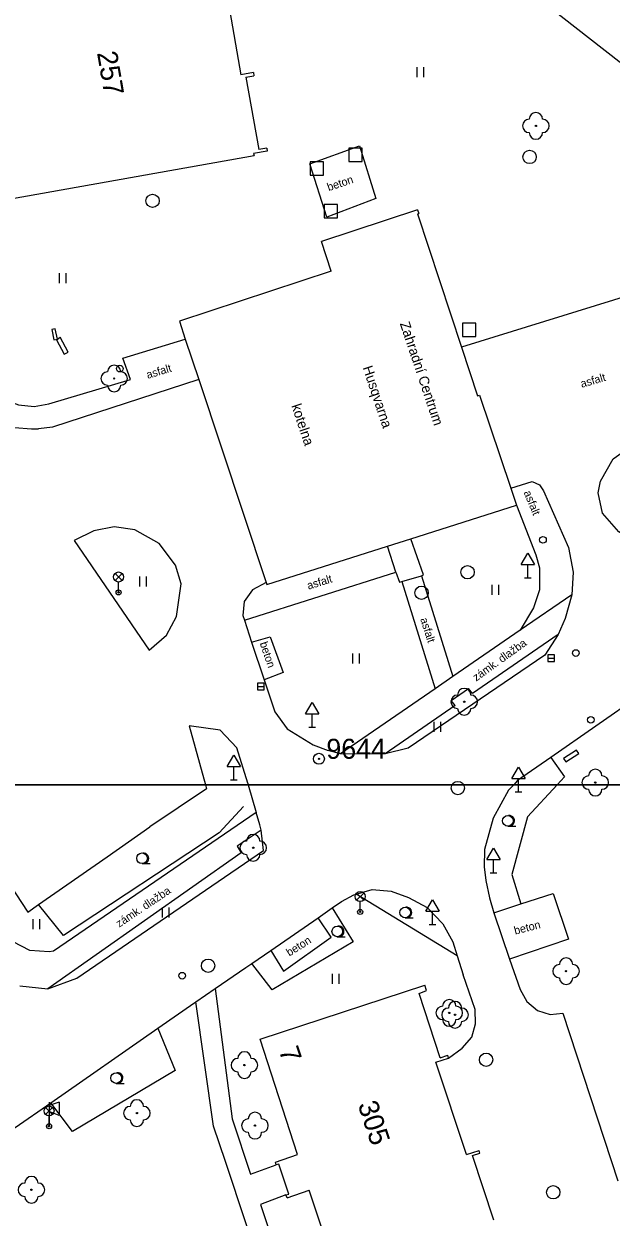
# Model space of a CAD drawing. Extents: x -492431 to -49218, y -1127123 to -112687.
# Drawn here: x -492287 to -492243, y -1127032.4 to -1126943 of the extents above; entities that cross this region are included whole.
import ezdxf

# ---------------------------------------------------------------- set-up
doc = ezdxf.new("R2010")
doc.units = 0
for name, color, linetype in [('Vrstva 10', 7, 'Continuous'), ('Vrstva 11', 7, 'Continuous'), ('Vrstva 21', 7, 'Continuous'), ('Vrstva 22', 7, 'Continuous'), ('Vrstva 24', 7, 'Continuous'), ('Vrstva 26', 7, 'Continuous'), ('Vrstva 27', 7, 'Continuous'), ('Vrstva 28', 7, 'Continuous'), ('Vrstva 31', 7, 'Continuous'), ('Vrstva 33', 7, 'Continuous'), ('Vrstva 34', 7, 'Continuous'), ('Vrstva 36', 7, 'Continuous'), ('Vrstva 40', 7, 'Continuous'), ('Vrstva 41', 7, 'Continuous'), ('Vrstva 43', 7, 'Continuous'), ('Vrstva 44', 7, 'Continuous'), ('Vrstva 5', 7, 'Continuous'), ('Vrstva 60', 7, 'Continuous'), ('Vrstva 63', 7, 'Continuous')]:
    doc.layers.add(name, color=color, linetype=linetype)

msp = doc.modelspace()

# ---------------------------------------------------------------- linework, layer by layer
at = {"layer": 'Vrstva 10'}
for p, q in [((-492265.6, -1126953.46), (-492261.86, -1126952.11)), ((-492261.86, -1126952.11), (-492260.64, -1126956.06)), ((-492264.31, -1126957.46), (-492265.6, -1126953.46)), ((-492260.64, -1126956.06), (-492264.31, -1126957.46)), ((-492279.61, -1126968.02), (-492274.92, -1126966.59)), ((-492279.03, -1126969.62), (-492279.61, -1126968.02)), ((-492285.15, -1126971.46), (-492279.03, -1126969.62)), ((-492287.72, -1126973.22), (-492286.45, -1126973.32)), ((-492286.45, -1126973.32), (-492285.91, -1126973.32)), ((-492281.77, -1126980.96), (-492283.25, -1126981.69)), ((-492280.25, -1126980.68), (-492281.77, -1126980.96)), ((-492278.7, -1126980.9), (-492280.25, -1126980.68)), ((-492276.87, -1126981.91), (-492278.7, -1126980.9)), ((-492283.25, -1126981.69), (-492277.62, -1126989.91)), ((-492275.66, -1126983.54), (-492276.87, -1126981.91)), ((-492275.23, -1126984.94), (-492275.66, -1126983.54)), ((-492275.57, -1126987.38), (-492275.23, -1126984.94)), ((-492245.95, -1126985.77), (-492246.47, -1126987.55)), ((-492276.32, -1126988.78), (-492275.57, -1126987.38)), ((-492246.47, -1126987.55), (-492246.98, -1126988.75)), ((-492277.62, -1126989.91), (-492276.32, -1126988.78)), ((-492246.98, -1126988.75), (-492253.39, -1126993.17)), ((-492246.98, -1126988.75), (-492247.98, -1126990.28)), ((-492247.98, -1126990.28), (-492258.22, -1126997.26)), ((-492255.01, -1126993.69), (-492253.69, -1126992.79)), ((-492253.39, -1126993.17), (-492253.69, -1126992.79)), ((-492254.71, -1126994.07), (-492259.95, -1126997.69)), ((-492254.71, -1126994.07), (-492255.01, -1126993.69)), ((-492261.1, -1126997.72), (-492263.3, -1126997.68)), ((-492259.95, -1126997.69), (-492261.1, -1126997.72)), ((-492258.22, -1126997.26), (-492259.95, -1126997.69)), ((-492270.23, -1126999.88), (-492270.2, -1127000)), ((-492270.2, -1127000), (-492269.62, -1127002.09)), ((-492269.62, -1127002.09), (-492284.8, -1127012.48)), ((-492269.34, -1127003.02), (-492269.62, -1127002.09)), ((-492280.77, -1127005.41), (-492277.57, -1127003.17)), ((-492269.24, -1127003.41), (-492269.34, -1127003.02)), ((-492269.24, -1127003.41), (-492271.04, -1127004.61)), ((-492269.06, -1127004.93), (-492269.24, -1127003.41)), ((-492270.73, -1127005.1), (-492285.22, -1127015.31)), ((-492283.04, -1127014.51), (-492269.06, -1127004.93)), ((-492271.04, -1127004.61), (-492270.73, -1127005.1)), ((-492286.57, -1127012.44), (-492287.83, -1127011.78)), ((-492285.11, -1127012.53), (-492286.57, -1127012.44)), ((-492284.8, -1127012.48), (-492285.11, -1127012.53)), ((-492285.22, -1127015.31), (-492283.04, -1127014.51)), ((-492287.32, -1127015.07), (-492285.22, -1127015.31))]:
    msp.add_line(p, q, dxfattribs=at)
for points in [[(-492272.49, -1126922.14), (-492263.24, -1126929.48), (-492236.88, -1126950.1), (-492234.89, -1126951.93), (-492232.6, -1126954.06), (-492229.07, -1126957.73), (-492220.98, -1126966.9), (-492221, -1126967.98), (-492221.64, -1126968.8), (-492231.06, -1126975.34), (-492237.59, -1126979.85), (-492240.73, -1126982.05)], [(-492291.44, -1126950.48), (-492294.66, -1126951.12), (-492295.46, -1126951.82), (-492295.99, -1126953.28), (-492294.2, -1126958.55), (-492290.72, -1126968.68), (-492290.05, -1126969.86), (-492288.83, -1126971), (-492287.42, -1126971.52), (-492286.24, -1126971.66), (-492285.15, -1126971.46)], [(-492240.73, -1126982.05), (-492242.43, -1126981.04), (-492243.65, -1126979.65), (-492243.98, -1126978.13), (-492243.82, -1126977.24), (-492242.86, -1126975.57), (-492242.18, -1126975.1), (-492234.4, -1126972.49), (-492237.99, -1126962.18), (-492254.22, -1126967.21)], [(-492273.91, -1126969.62), (-492284.88, -1126973.2), (-492285.91, -1126973.32)], [(-492250.54, -1126977.76), (-492248.94, -1126977.27), (-492248.39, -1126977.51), (-492248.07, -1126977.98), (-492246.22, -1126982.22), (-492245.86, -1126984.06), (-492245.95, -1126985.77)], [(-492250.11, -1126979.04), (-492248.65, -1126982.76), (-492248.39, -1126983.74), (-492248.37, -1126985.38), (-492248.82, -1126986.74), (-492249.82, -1126988.41), (-492254.88, -1126991.89)], [(-492257.22, -1126984.35), (-492257.08, -1126984.27), (-492258.02, -1126981.56)], [(-492270.49, -1126987.67), (-492259.15, -1126984.07)], [(-492259.15, -1126984.07), (-492258.86, -1126984.82), (-492258.69, -1126984.76)], [(-492257.22, -1126984.35), (-492254.88, -1126991.89)], [(-492268.86, -1126984.83), (-492269.88, -1126985.38), (-492270.51, -1126986.26), (-492270.61, -1126987.31)], [(-492258.69, -1126984.76), (-492256.2, -1126992.81)], [(-492270.61, -1126987.31), (-492270.49, -1126987.67)], [(-492270.49, -1126987.67), (-492269.96, -1126989.31)], [(-492269.96, -1126989.31), (-492268.56, -1126988.92), (-492267.59, -1126991.6), (-492269, -1126992.13)], [(-492269.96, -1126989.31), (-492269, -1126992.13), (-492268.21, -1126994.53), (-492267.29, -1126995.81), (-492265.34, -1126997.02), (-492264.22, -1126997.44)], [(-492237.41, -1126990.92), (-492247.53, -1126997.96), (-492250.02, -1126999.69)], [(-492256.2, -1126992.81), (-492263.3, -1126997.68)], [(-492270.23, -1126999.88), (-492271.07, -1126997.24), (-492272.31, -1126995.92), (-492274.63, -1126995.59), (-492273.41, -1127000)], [(-492263.3, -1126997.68), (-492264.22, -1126997.44)], [(-492250.02, -1126999.69), (-492250.31, -1127000)], [(-492273.41, -1127000), (-492273.32, -1127000.31), (-492277.57, -1127003.17)], [(-492250.31, -1127000), (-492250.71, -1127000.42), (-492251.85, -1127002.52), (-492252.49, -1127004.86), (-492252.53, -1127006.16), (-492252.4, -1127007.18), (-492252.12, -1127008.48), (-492251.8, -1127009.61)], [(-492289.34, -1127005.59), (-492286.73, -1127009.56), (-492285.91, -1127008.99), (-492280.77, -1127005.41)], [(-492264.97, -1127009.97), (-492263.91, -1127009.24), (-492263.22, -1127008.76), (-492262.3, -1127008.27), (-492262.13, -1127008.22), (-492260.93, -1127007.87), (-492259.5, -1127007.99), (-492258.19, -1127008.45), (-492256.79, -1127009.2), (-492255.63, -1127010.42), (-492254.87, -1127011.79), (-492254.54, -1127012.84), (-492254.09, -1127014.25)], [(-492251.8, -1127009.61), (-492249.77, -1127008.94), (-492247.36, -1127008.15), (-492246.22, -1127011.59), (-492250.62, -1127013.07)], [(-492251.8, -1127009.61), (-492250.62, -1127013.07), (-492249.84, -1127015.35), (-492249.33, -1127016.26), (-492248.54, -1127016.92), (-492247.57, -1127017.23), (-492246.64, -1127017.13), (-492242.51, -1127029.7)], [(-492268.5, -1127012.44), (-492267.56, -1127013.99), (-492263.99, -1127011.44), (-492264.97, -1127009.97)], [(-492268.5, -1127012.44), (-492264.97, -1127009.97)], [(-492288.26, -1127040.02), (-492289.42, -1127036.56), (-492289.89, -1127035.11), (-492290.26, -1127032.72), (-492290.1, -1127029.83), (-492289.45, -1127028.22), (-492288.65, -1127026.91), (-492287.66, -1127025.7), (-492284.99, -1127023.84), (-492276.97, -1127018.26), (-492274.21, -1127016.34), (-492274.13, -1127016.28), (-492272.68, -1127015.29), (-492270.39, -1127013.71), (-492269.93, -1127013.4), (-492268.5, -1127012.44)], [(-492255.2, -1127020.49), (-492254.18, -1127019.76), (-492253.46, -1127018.94), (-492253.17, -1127017.94), (-492253.21, -1127016.86), (-492254.09, -1127014.25)], [(-492272.68, -1127015.29), (-492271.4, -1127025.05), (-492270.03, -1127029.19), (-492268.1, -1127028.5)], [(-492271.91, -1127028.26), (-492272.82, -1127025.61), (-492274.13, -1127016.28)], [(-492259.59, -1127065.402), (-492271.91, -1127028.26)], [(-492267.38, -1127030.76), (-492269.28, -1127031.47), (-492265.13, -1127043.91), (-492264.31, -1127046.41), (-492262.43, -1127045.76)]]:
    msp.add_lwpolyline(points, dxfattribs=at)
at = {"layer": 'Vrstva 11'}
for points in [[(-492259.15, -1126984.07), (-492259.77, -1126982.12)], [(-492258.69, -1126984.76), (-492257.22, -1126984.35)], [(-492245.95, -1126985.77), (-492249.82, -1126988.41)], [(-492254.88, -1126991.89), (-492256.2, -1126992.81)]]:
    msp.add_lwpolyline(points, dxfattribs=at)
at = {"layer": 'Vrstva 21'}
for points in [[(-492247.53, -1126997.96), (-492246.5, -1126999.4), (-492247.05, -1127000)], [(-492247.05, -1127000), (-492249.28, -1127002.42), (-492250.45, -1127006.73), (-492249.77, -1127008.94)], [(-492270.55, -1127001.64), (-492272.38, -1127003.62), (-492284.04, -1127011.31), (-492285.91, -1127008.99)], [(-492254.54, -1127012.84), (-492262.13, -1127008.22)], [(-492263.91, -1127009.24), (-492262.34, -1127011.79), (-492268.42, -1127015.38), (-492269.93, -1127013.4)], [(-492276.97, -1127018.26), (-492275.68, -1127021.43), (-492283.38, -1127025.99), (-492284.99, -1127023.84)]]:
    msp.add_lwpolyline(points, dxfattribs=at)
at = {"layer": 'Vrstva 22'}
for centre in [(-492248.65, -1126950.61), (-492280.25, -1126969.55), (-492254.02, -1126993.78), (-492244.2, -1126999.84), (-492269.83, -1127004.73), (-492246.39, -1127013.98), (-492255.14, -1127017.11), (-492254.71, -1127017.25), (-492270.49, -1127021.02), (-492278.55, -1127024.62), (-492269.7, -1127025.56), (-492286.45, -1127030.37)]:
    msp.add_circle(centre, 0.05, dxfattribs=at)
for centre, start, end in [((-492248.65, -1126950.11), 360, 180), ((-492249.15, -1126950.61), 90, 270), ((-492248.15, -1126950.61), 270, 90), ((-492248.65, -1126951.11), 180, 0), ((-492280.75, -1126969.55), 90, 270), ((-492280.25, -1126969.05), 360, 180), ((-492279.75, -1126969.55), 270, 90), ((-492280.25, -1126970.05), 180, 0), ((-492254.52, -1126993.78), 90, 270), ((-492254.02, -1126993.28), 360, 180), ((-492253.52, -1126993.78), 270, 90), ((-492254.02, -1126994.28), 180, 0), ((-492244.2, -1126999.34), 360, 180), ((-492244.7, -1126999.84), 90, 270), ((-492243.7, -1126999.84), 270, 90), ((-492244.2, -1127000.34), 180, 0), ((-492270.33, -1127004.73), 90, 270), ((-492269.83, -1127004.23), 360, 180), ((-492269.33, -1127004.73), 270, 90), ((-492269.83, -1127005.23), 180, 0), ((-492246.39, -1127013.48), 360, 180), ((-492246.89, -1127013.98), 90, 270), ((-492245.89, -1127013.98), 270, 90), ((-492246.39, -1127014.48), 180, 0), ((-492255.64, -1127017.11), 90, 270), ((-492255.21, -1127017.25), 90, 270), ((-492255.14, -1127016.61), 360, 180), ((-492254.71, -1127016.75), 360, 180), ((-492254.64, -1127017.11), 270, 90), ((-492254.21, -1127017.25), 270, 90), ((-492255.14, -1127017.61), 180, 0), ((-492254.71, -1127017.75), 180, 0), ((-492270.49, -1127020.52), 360, 180), ((-492270.99, -1127021.02), 90, 270), ((-492269.99, -1127021.02), 270, 90), ((-492270.49, -1127021.52), 180, 0), ((-492278.55, -1127024.12), 360, 180), ((-492279.05, -1127024.62), 90, 270), ((-492278.05, -1127024.62), 270, 90), ((-492269.7, -1127025.06), 360, 180), ((-492278.55, -1127025.12), 180, 0), ((-492270.2, -1127025.56), 90, 270), ((-492269.2, -1127025.56), 270, 90), ((-492269.7, -1127026.06), 180, 0), ((-492286.95, -1127030.37), 90, 270), ((-492286.45, -1127029.87), 360, 180), ((-492285.95, -1127030.37), 270, 90), ((-492286.45, -1127030.87), 180, 0)]:
    msp.add_arc(centre, 0.5, start, end, dxfattribs=at)
at = {"layer": 'Vrstva 24'}
for p, q in [((-492284.91, -1126965.88), (-492284.76, -1126966.64)), ((-492284.57, -1126966.65), (-492283.99, -1126967.72)), ((-492283.7, -1126967.57), (-492284.3, -1126966.45)), ((-492283.99, -1126967.72), (-492283.7, -1126967.57)), ((-492246.4, -1126998.29), (-492245.43, -1126997.67)), ((-492245.43, -1126997.67), (-492245.6, -1126997.41))]:
    msp.add_line(p, q, dxfattribs=at)
for points in [[(-492284.76, -1126966.64), (-492284.5, -1126966.59), (-492284.67, -1126965.82), (-492284.91, -1126965.88)], [(-492284.57, -1126966.65), (-492284.5, -1126966.59), (-492284.3, -1126966.45)], [(-492245.6, -1126997.41), (-492246.58, -1126998.04), (-492246.4, -1126998.29)]]:
    msp.add_lwpolyline(points, dxfattribs=at)
at = {"layer": 'Vrstva 26'}
for points in [[(-492262.66, -1126953.27), (-492261.66, -1126953.27), (-492261.66, -1126952.27), (-492262.66, -1126952.27)], [(-492265.57, -1126954.31), (-492264.57, -1126954.31), (-492264.57, -1126953.31), (-492265.57, -1126953.31)], [(-492264.51, -1126957.5), (-492263.51, -1126957.5), (-492263.51, -1126956.5), (-492264.51, -1126956.5)], [(-492254.14, -1126966.39), (-492253.14, -1126966.39), (-492253.14, -1126965.39), (-492254.14, -1126965.39)]]:
    msp.add_lwpolyline(points, close=True, dxfattribs=at)
at = {"layer": 'Vrstva 27'}
for p, q in [((-492247.75, -1126990.51), (-492247.25, -1126990.51)), ((-492269.51, -1126992.65), (-492269.01, -1126992.65))]:
    msp.add_line(p, q, dxfattribs=at)
for points in [[(-492247.75, -1126990.76), (-492247.25, -1126990.76), (-492247.25, -1126990.26), (-492247.75, -1126990.26)], [(-492269.51, -1126992.9), (-492269.01, -1126992.9), (-492269.01, -1126992.4), (-492269.51, -1126992.4)]]:
    msp.add_lwpolyline(points, close=True, dxfattribs=at)
for centre in [(-492249.12, -1126952.94), (-492277.37, -1126956.23), (-492253.77, -1126984.07), (-492257.22, -1126985.61), (-492254.5, -1127000.25), (-492273.21, -1127013.57), (-492252.38, -1127020.62), (-492247.35, -1127030.56)]:
    msp.add_circle(centre, 0.5, dxfattribs=at)
at = {"layer": 'Vrstva 28'}
for centre in [(-492279.82, -1126968.81), (-492248.12, -1126981.65), (-492244.53, -1126995.14)]:
    msp.add_circle(centre, 0.25, dxfattribs=at)
at = {"layer": 'Vrstva 31'}
for centre in [(-492245.66, -1126990.13), (-492275.16, -1127014.32)]:
    msp.add_circle(centre, 0.25, dxfattribs=at)
at = {"layer": 'Vrstva 33'}
for p, q in [((-492280.185, -1126984.165), (-492279.655, -1126984.695)), ((-492280.185, -1126984.695), (-492279.655, -1126984.165)), ((-492279.92, -1126985.58), (-492279.92, -1126984.805)), ((-492262.085, -1127008.125), (-492261.555, -1127008.655)), ((-492262.085, -1127008.655), (-492261.555, -1127008.125)), ((-492261.82, -1127009.54), (-492261.82, -1127008.765)), ((-492285.13, -1127023.81), (-492285.13, -1127025.56)), ((-492284.38, -1127023.81), (-492285.13, -1127024.06)), ((-492284.38, -1127023.81), (-492284.38, -1127024.81)), ((-492285.395, -1127024.195), (-492284.865, -1127024.725)), ((-492285.395, -1127024.725), (-492284.865, -1127024.195)), ((-492284.38, -1127024.81), (-492285.13, -1127024.51)), ((-492285.13, -1127025.61), (-492285.13, -1127024.835))]:
    msp.add_line(p, q, dxfattribs=at)
for centre, radius in [((-492279.92, -1126984.43), 0.375), ((-492279.92, -1126985.58), 0.19), ((-492279.92, -1126985.58), 0.05), ((-492261.82, -1127008.39), 0.375), ((-492261.82, -1127009.54), 0.19), ((-492261.82, -1127009.54), 0.05), ((-492285.13, -1127024.46), 0.375), ((-492285.13, -1127025.61), 0.19), ((-492285.13, -1127025.61), 0.05)]:
    msp.add_circle(centre, radius, dxfattribs=at)
at = {"layer": 'Vrstva 34'}
for p, q in [((-492249.75, -1126983.49), (-492249.25, -1126982.64)), ((-492249.25, -1126982.64), (-492248.75, -1126983.49)), ((-492249.75, -1126983.49), (-492248.75, -1126983.49)), ((-492249.25, -1126984.49), (-492249.25, -1126983.49)), ((-492249.5, -1126984.49), (-492249, -1126984.49)), ((-492265.91, -1126994.7), (-492265.41, -1126993.85)), ((-492265.41, -1126993.85), (-492264.91, -1126994.7)), ((-492265.91, -1126994.7), (-492264.91, -1126994.7)), ((-492265.41, -1126995.7), (-492265.41, -1126994.7)), ((-492265.66, -1126995.7), (-492265.16, -1126995.7)), ((-492271.78, -1126998.63), (-492271.28, -1126997.78)), ((-492271.28, -1126997.78), (-492270.78, -1126998.63)), ((-492271.78, -1126998.63), (-492270.78, -1126998.63)), ((-492271.28, -1126999.63), (-492271.28, -1126998.63)), ((-492250.45, -1126999.53), (-492249.95, -1126998.68)), ((-492249.95, -1126998.68), (-492249.45, -1126999.53)), ((-492271.53, -1126999.63), (-492271.03, -1126999.63)), ((-492250.45, -1126999.53), (-492249.45, -1126999.53)), ((-492249.95, -1127000.53), (-492249.95, -1126999.53)), ((-492250.2, -1127000.53), (-492249.7, -1127000.53)), ((-492252.32, -1127005.6), (-492251.82, -1127004.75)), ((-492251.82, -1127004.75), (-492251.32, -1127005.6)), ((-492252.32, -1127005.6), (-492251.32, -1127005.6)), ((-492251.82, -1127006.6), (-492251.82, -1127005.6)), ((-492252.07, -1127006.6), (-492251.57, -1127006.6)), ((-492256.89, -1127009.47), (-492256.39, -1127008.62)), ((-492256.39, -1127008.62), (-492255.89, -1127009.47)), ((-492256.89, -1127009.47), (-492255.89, -1127009.47)), ((-492256.39, -1127010.47), (-492256.39, -1127009.47)), ((-492256.64, -1127010.47), (-492256.14, -1127010.47))]:
    msp.add_line(p, q, dxfattribs=at)
at = {"layer": 'Vrstva 36'}
for p, q in [((-492257.55, -1126946.95), (-492257.55, -1126946.2)), ((-492257.05, -1126946.95), (-492257.05, -1126946.2)), ((-492284.35, -1126962.4), (-492284.35, -1126961.65)), ((-492283.85, -1126962.4), (-492283.85, -1126961.65)), ((-492278.33, -1126985.14), (-492278.33, -1126984.39)), ((-492277.83, -1126985.14), (-492277.83, -1126984.39)), ((-492251.92, -1126985.76), (-492251.92, -1126985.01)), ((-492251.42, -1126985.76), (-492251.42, -1126985.01)), ((-492262.38, -1126990.91), (-492262.38, -1126990.16)), ((-492261.88, -1126990.91), (-492261.88, -1126990.16)), ((-492256.27, -1126996.04), (-492256.27, -1126995.29)), ((-492255.77, -1126996.04), (-492255.77, -1126995.29)), ((-492250.75, -1127003.11), (-492250.65, -1127003.11)), ((-492250.65, -1127003.11), (-492250.15, -1127003.11)), ((-492278.16, -1127005.92), (-492278.06, -1127005.92)), ((-492278.06, -1127005.92), (-492277.56, -1127005.92)), ((-492276.63, -1127009.95), (-492276.63, -1127009.2)), ((-492276.13, -1127009.95), (-492276.13, -1127009.2)), ((-492286.31, -1127010.84), (-492286.31, -1127010.09)), ((-492285.81, -1127010.84), (-492285.81, -1127010.09)), ((-492258.45, -1127009.98), (-492258.35, -1127009.98)), ((-492258.35, -1127009.98), (-492257.85, -1127009.98)), ((-492263.53, -1127011.4), (-492263.43, -1127011.4)), ((-492263.43, -1127011.4), (-492262.93, -1127011.4)), ((-492263.88, -1127014.93), (-492263.88, -1127014.18)), ((-492263.38, -1127014.93), (-492263.38, -1127014.18)), ((-492280.1, -1127022.39), (-492280, -1127022.39)), ((-492280, -1127022.39), (-492279.5, -1127022.39))]:
    msp.add_line(p, q, dxfattribs=at)
for centre in [(-492250.75, -1127002.71), (-492278.16, -1127005.52), (-492258.45, -1127009.58), (-492263.53, -1127011), (-492280.1, -1127021.99)]:
    msp.add_circle(centre, 0.4, dxfattribs=at)
for centre in [(-492250.65, -1127002.71), (-492278.06, -1127005.52), (-492258.35, -1127009.58), (-492263.43, -1127011), (-492280, -1127021.99)]:
    msp.add_arc(centre, 0.4, 259.69515, 97.18076, dxfattribs=at)
at = {"layer": 'Vrstva 5'}
for p, q in [((-492270.38, -1126946.96), (-492269.79, -1126946.86)), ((-492270.38, -1126946.96), (-492269.42, -1126952.39)), ((-492269.82, -1126946.62), (-492269.79, -1126946.86)), ((-492268.82, -1126952.28), (-492269.42, -1126952.39)), ((-492268.82, -1126952.28), (-492268.78, -1126952.51)), ((-492289.36, -1126956.32), (-492269.77, -1126952.84)), ((-492268.78, -1126952.51), (-492269.8, -1126952.69)), ((-492269.8, -1126952.69), (-492269.77, -1126952.84)), ((-492257.53, -1126956.9), (-492264.72, -1126959.28)), ((-492257.53, -1126956.9), (-492257.43, -1126957.17)), ((-492257.52, -1126957.2), (-492257.43, -1126957.17)), ((-492263.99, -1126961.5), (-492264.72, -1126959.28)), ((-492263.99, -1126961.5), (-492275.36, -1126965.26)), ((-492253.02, -1126970.85), (-492252.87, -1126970.8)), ((-492269.32, -1127019.09), (-492256.98, -1127015.03)), ((-492257.4, -1127015.66), (-492256.84, -1127015.44)), ((-492255.83, -1127020.47), (-492257.4, -1127015.66)), ((-492256.84, -1127015.44), (-492256.98, -1127015.03)), ((-492266.52, -1127027.73), (-492269.32, -1127019.09)), ((-492255.83, -1127020.47), (-492255.26, -1127020.28)), ((-492255.2, -1127020.49), (-492255.26, -1127020.28)), ((-492256.16, -1127020.8), (-492255.2, -1127020.49)), ((-492253.86, -1127027.73), (-492256.16, -1127020.8)), ((-492253.86, -1127027.73), (-492252.9, -1127027.42)), ((-492252.84, -1127027.63), (-492252.9, -1127027.42)), ((-492268.17, -1127028.29), (-492266.52, -1127027.73)), ((-492268.1, -1127028.5), (-492268.17, -1127028.29)), ((-492253.39, -1127027.81), (-492252.84, -1127027.63)), ((-492251.81, -1127032.64), (-492253.39, -1127027.81)), ((-492267.92, -1127028.44), (-492268.1, -1127028.5)), ((-492267.17, -1127030.69), (-492267.92, -1127028.44)), ((-492267.38, -1127030.76), (-492267.17, -1127030.69)), ((-492267.29, -1127030.97), (-492267.38, -1127030.76)), ((-492267.29, -1127030.97), (-492265.64, -1127030.41))]:
    msp.add_line(p, q, dxfattribs=at)
for points in [[(-492271.68, -1126941.46), (-492270.77, -1126946.79)], [(-492269.82, -1126946.62), (-492270.77, -1126946.79)], [(-492257.52, -1126957.2), (-492254.22, -1126967.21), (-492253.02, -1126970.85)], [(-492275.36, -1126965.26), (-492274.92, -1126966.59), (-492273.91, -1126969.62), (-492268.86, -1126984.83), (-492268.8, -1126985)], [(-492252.87, -1126970.8), (-492250.54, -1126977.76), (-492250.11, -1126979.04)], [(-492268.8, -1126985), (-492259.77, -1126982.12), (-492258.02, -1126981.56), (-492250.11, -1126979.04)], [(-492263.6, -1127036.56), (-492265.64, -1127030.41)]]:
    msp.add_lwpolyline(points, dxfattribs=at)
at = {"layer": 'Vrstva 60'}
for p, q in [((-492431.031, -1127000), (-492166.731, -1127000)), ((-492166.731, -1127000), (-492431.031, -1127000))]:
    msp.add_line(p, q, dxfattribs=at)
at = {"layer": 'Vrstva 63'}
for radius in [0.412, 0.05]:
    msp.add_circle((-492264.91, -1126998.06), radius, dxfattribs=at)

# ---------------------------------------------------------------- texts
at = {"layer": 'Vrstva 40'}
for s, rotation, p in [('beton', 18.57503, (-492264.179, -1126955.509)), ('asfalt', 16.77763, (-492277.738, -1126969.575)), ('asfalt', 16.39975, (-492245.212, -1126970.248)), ('asfalt', 292.29006, (-492249.575, -1126978.088)), ('asfalt', 17.1281, (-492265.694, -1126985.382)), ('asfalt', 287.83542, (-492257.325, -1126987.584)), ('beton', 288.82376, (-492269.353, -1126989.394)), ('zámk. dlažba', 35.81113, (-492253.119, -1126992.272)), ('zámk. dlažba', 33.99056, (-492279.868, -1127010.724)), ('beton', 14.44541, (-492250.204, -1127011.244)), ('beton', 32.06846, (-492267.127, -1127012.889))]:
    msp.add_text(s, height=0.6, rotation=rotation, dxfattribs=at).set_placement(p)
at = {"layer": 'Vrstva 41'}
for s, rotation, p in [('Zahradní Centrum', 288.51835, (-492258.855, -1126965.429)), ('Husqvarna', 288.38269, (-492261.639, -1126968.734)), ('kotelna', 288.38269, (-492266.983, -1126971.585))]:
    msp.add_text(s, height=0.75, rotation=rotation, dxfattribs=at).set_placement(p)
at = {"layer": 'Vrstva 43'}
for s, rotation, p in [('257', 279.76251, (-492281.54, -1126945.128)), ('305', 288.43216, (-492262.013, -1127023.984))]:
    msp.add_text(s, height=1.5, rotation=rotation, dxfattribs=at).set_placement(p)
at = {"layer": 'Vrstva 44'}
msp.add_text('7', height=1.5, rotation=288.43216, dxfattribs=at).set_placement((-492267.932, -1127019.905))
at = {"layer": 'Vrstva 63'}
msp.add_text(' 9644', height=1.5, dxfattribs=at).set_placement((-492264.91, -1126998.06))

doc.saveas('drawing.dxf')
